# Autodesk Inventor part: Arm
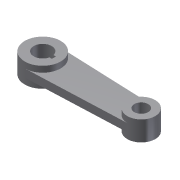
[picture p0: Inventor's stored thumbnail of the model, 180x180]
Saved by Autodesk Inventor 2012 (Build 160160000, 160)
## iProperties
Created: 2009-04
Part Number: Arm
Material: Default
Document SubType Name: Modeling
Designer: Sham
Density: 1 g/cm^3
Sheet Metal Width: 0.000 mm
Sheet Metal Length: 0.000 mm
Sheet Metal Area: 0.000 mm^2
Mass: 1315.43 g
Surface Area: 1371.18 cm^2
Volume: 1315.43 cm^3
Author: Sham
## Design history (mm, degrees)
sketch "Sketch1"
  geometry: L1 (27.436, 6.3)-(35.136, 6.3); L2 (35.136, 6.3)-(35.136, -6.3); L3 (35.136, -6.3)-(27.436, -6.3); C1 r 56.25 at (0, 0); C2 r 43.75 at (309, 0); C3 r 21.9 at (309, 0); A1 r 28.15 centre (0, 0) between (27.436, 6.3) and (27.436, -6.3); 1 further point
  constraints: 6 end point, 4 centre point, 3 coincident, 2 point on circle, 1 horizontal, 1 parallel, 1 perpendicular, 1 other
  dimensions: "d0" = 112.5 diameter of C1; "d2" = 87.5 diameter of C2; "d3" = 56.3 diameter of A1; "d4" = 43.8 diameter of C3; "d7" = 12.6 distance of L1.end L2.end; "d8" = 7.7 distance of L1.start L1.end; "d9" = 7.7 distance of L2.end L3.end
extrude "Extrusion1" join sketch "Sketch1" stored distance "d5" = 62.5; taper "d6" = 0 deg
sketch "Sketch2"
  geometry: L1 (2.275, 56.204)-(310.77, 43.714); L2 (2.275, -56.204)-(310.77, -43.714); A1 r 56.25 centre (0, 0) between (2.275, 56.204) and (2.275, -56.204) reference; A2 r 43.75 centre (309, 0) between (310.77, 43.714) and (310.77, -43.714) reference
  constraints: 4 end point, 4 point on circle, 4 tangent
extrude "Extrusion2" join sketch "Sketch2" stored distance "d10" = 25; taper "d11" = 0 deg
body "Solid1"
other parameters: "Thickness" = 0.5, "BendRadius" = 0.5 (= Thickness), "BendReliefWidth" = 0.5 (= Thickness), "BendReliefDepth" = 0.25 (= 0.5 x Thickness), "CornerReliefSize" = 2 (= 4 x Thickness), "SeamGap" = 0.01, "MinimumRemnant" = 1 (= 2 x Thickness), "TransitionRadius" = 0.5 (= BendRadius), "JacobiRadiusSize" = 0.5 (= BendRadius), "GapSize" = 0.5 (= Thickness)
